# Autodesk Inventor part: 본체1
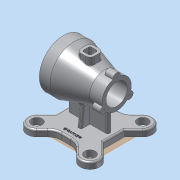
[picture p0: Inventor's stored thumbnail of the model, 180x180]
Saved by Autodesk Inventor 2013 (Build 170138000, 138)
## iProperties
Created: 2018-03
Part Number: 본체1
Material: 알루미늄 6061
Document SubType Name: Modeling
Designer: dgall
Density: 2.71 g/cm^3
Mass: 988.597 g
Surface Area: 870.918 cm^2
Volume: 364.796 cm^3
Author: dgall
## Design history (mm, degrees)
sketch "스케치1"
  geometry: L1 (-50, 0)-(50, 0); L2 (-50, 0)-(-50, 45); L3 (-50, 45)-(-30, 45); L4 (27, 27.5)-(50, 27.5); L5 (50, 27.5)-(50, 0); L6 (-30, 45)-(27, 27.5); 1 further point
  constraints: 12 end point, 3 perpendicular, 1 horizontal, 1 midpoint
  dimensions: "d0" = 90 diameter of L2.end L1; "d2" = 20 distance from line of L3.end L2; "d6" = 55 diameter of L4 L1; "d34" = 77 horizontal distance of L2.end L4.start; "d35" = 100 distance between parallel lines of L5 L2; "d36" = 50 distance from line of L5 point (0, 0)
revolve "회전1" sketch "스케치1" stored, may be unused: angle "d11" = 90 deg
sketch "스케치9"
  geometry: L1 (-50, 0)-(50, 0); L2 (50, 35)-(27, 35); L3 (27, 35)-(27, 26); L4 (27, 26)-(-20, 26); L5 (-20, 26)-(-20, 20); L6 (-20, 20)-(-50, 20); L7 (50, 35)-(50, 0); L8 (-50, 20)-(-50, 0); 1 further point
  constraints: 16 end point, 5 parallel, 2 perpendicular, 1 horizontal, 1 midpoint
  dimensions: "d37" = 100 horizontal distance of L2.start L6.end; "d39" = 70 diameter of L2 L1; "d40" = 23 distance of L2.start L2.end; "d41" = 52 diameter of L4 L1; "d42" = 47 distance between parallel lines of L3 L5; "d43" = 40 diameter of L6 L1; "d44" = 27 distance from line of point (0, 0) L3
revolve "회전3" sketch "스케치9" stored, may be unused: angle "d45" = 90 deg
node "작업 평면2"
sketch "스케치10"
  geometry: L1 (-69.444, 0)-(69.444, 0); L2 (0, 48.611)-(0, -44.444); L3 (-12.5, 12.5)-(12.5, 12.5); L4 (12.5, 12.5)-(12.5, -12.5); L5 (12.5, -12.5)-(-12.5, -12.5); L6 (-12.5, -12.5)-(-12.5, 12.5); 2 further points
  constraints: 12 end point, 2 horizontal, 2 midpoint, 2 parallel, 2 perpendicular, 2 point on line
  dimensions: "d47" = 12.5 distance between parallel lines of L1 L3; "d50" = 12.5 distance between parallel lines of L6 L2; "d51" = 12.5 distance between parallel lines of L4 L2; "d60" = 25 distance between parallel lines of L5 L3
extrude "돌출2" join sketch "스케치10" stored distance "d52" = 10; taper "d53" = 0 deg
sketch "스케치11"
  geometry: L1 (-7.5, 7.5)-(7.5, 7.5); L2 (7.5, 7.5)-(7.5, -7.5); L3 (7.5, -7.5)-(-7.5, -7.5); L4 (-7.5, -7.5)-(-7.5, 7.5); 1 further point
  constraints: 8 end point, 2 parallel, 1 horizontal, 1 perpendicular
  dimensions: "d54" = 7.5 distance from line of L4 point (0, 0); "d55" = 7.5 distance from line of point (0, 0) L2; "d56" = 15 distance between parallel lines of L3 L1; "d57" = 7.5 distance from line of L1 point (0, 0)
extrude "돌출3" cut sketch "스케치11" stored distance "d58" = 10; taper "d59" = 0 deg
fillet "모깎기1" dims "d61" = 8
fillet "모깎기2" dims "d62" = 3
fillet "모깎기3" dims "d63" = 1
node "작업 평면3"
sketch "스케치12"
  geometry: L1 (-45, 45)-(45, 45); L2 (45, 45)-(45, -45); L3 (45, -45)-(-45, -45); L4 (-45, -45)-(-45, 45); L5 (-45, 0)-(45, 0); L6 (60.483, 35.239)-(45, 19.755); L7 (35.239, 60.483)-(19.755, 45); L8 (-65.473, 65.473)-(65.473, -65.473); L9 (62.225, 62.225)-(-62.512, -62.512); L10 (-40.017, 65.473)-(-19.544, 45); L11 (-65.473, 40.017)-(-45, 19.544); L12 (-25.456, 0)-(36.77, 62.225); L13 (-37.056, -62.512)-(-19.544, -45); L14 (0, -25.456)-(62.225, 36.77); L15 (0, 25.456)-(25.456, 0); L16 (45, -19.544)-(65.473, -40.017); L17 (-25.456, 0)-(0, -25.456); L18 (19.544, -45)-(40.017, -65.473); L19 (-62.512, -37.056)-(-33, -7.544); A1 r 70 centre (0, 0) between (60.483, 35.239) and (35.239, 60.483); A2 r 18 centre (-52.745, 52.745) between (-36.227, 59.897) and (-59.897, 36.227); A3 r 18 centre (-49.784, -49.784) between (-62.512, -62.512) and (-37.056, -62.512); A4 r 18 centre (49.497, 49.497) between (60.483, 35.239) and (35.239, 60.483); A5 r 18 centre (52.745, -52.745) between (65.473, -65.473) and (40.017, -65.473); 5 further points
  constraints: 38 end point, 20 point on circle, 18 parallel, 15 point on line, 6 midpoint, 5 centre point, 3 perpendicular, 1 coincident, 1 horizontal, 1 tangent
  dimensions: "d65" = 45 distance from line of L4 point (0, 0); "d67" = 45 distance from line of point (0, 0) L1; "d69" = 90 distance between parallel lines of L3 L1; "d70" = 90 distance between parallel lines of L2 L4; "d71" = 140 diameter of A1; "d74" = 36 diameter of A3; "d77" = 36 diameter of A4; "d78" = 36 diameter of A5; "d83" = 45 deg angle of L5 L8; "d86" = 36 diameter of A2; "d87" = 45 deg angle of L5 L9; "d90" = 18 distance between parallel lines of L13 L9
extrude "돌출4" join sketch "스케치12" distance "d92" = 12; taper "d93" = 0 deg
sketch "스케치13"
  geometry: L1 (36.77, 62.225)-(-12.728, 12.728) reference; L2 (-12.728, 12.728)-(-45, 45) reference; L3 (-45, 45)-(-19.544, 45) reference; L4 (-45, 19.544)-(-45, -32.432) reference; L5 (-19.544, 45)-(19.544, 45); 1 further point
  constraints: 2 end point, 1 perpendicular, 1 point on line
extrude "돌출5" join sketch "스케치13" distance "d94" = 12; taper "d95" = 0 deg
sketch "스케치14"
  geometry: L1 (-32.432, -45)-(19.544, -45) reference; L2 (-65.473, 40.017)-(-45, 19.544) reference; L3 (-45, 19.544)-(-45, -32.432) reference; L4 (-37.056, -62.512)-(-19.544, -45); L5 (-62.512, -37.056)-(-45, -19.544); A1 r 18 centre (-49.784, -49.784) between (-45, -32.432) and (-32.432, -45) reference; 1 further point
  constraints: 4 end point, 2 point on circle, 2 point on line, 1 parallel, 1 perpendicular
  dimensions: "d96" = 18 distance from line of L4 point (0, 0); "d97" = 18 distance from line of point (0, 0) L5
extrude "돌출6" join sketch "스케치14" distance "d98" = 12; taper "d99" = 0 deg
fillet "모깎기4" dims "d100" = 25
sketch "스케치18"
  geometry: L1 (-45, 19.544)-(-45, -19.544) reference; L2 (0, 0)-(-37, 0); L3 (0, 0)-(37, 0); L4 (-37.056, -4)-(36.944, -4); L5 (-37.056, 4)-(36.944, 4); L6 (-37.056, 4)-(-37.056, -4); L7 (36.944, 4)-(36.944, -4)
  constraints: 12 end point, 2 equal length, 2 perpendicular
  dimensions: "d111" = 4 distance between parallel lines of L5 L2; "d112" = 4 distance between parallel lines of L2 L4; "d115" = 74 distance between parallel lines of L6 L7
extrude "돌출7" join sketch "스케치18" stored distance "d116" = 12; taper "d117" = 0 deg
sketch "스케치20"
  geometry: L1 (-24, -109.58)-(-24, -45); L2 (-24, -109.58)-(-18, -41); L3 (-19.544, -70)-(-37.056, -70) reference; 1 further point
  constraints: 4 end point, 2 point on line, 1 vertical
  dimensions: "d118" = 24 distance from line of point (0, 0) L1; "d119" = 95 deg angle of L3 L2
feature "리브1" sketch "스케치20" dims "d120" = 1, "d121" = 8, "d122" = 0, "d123" = 0, "d124" = 1, "d125" = 1
sketch "스케치21"
  geometry: L1 (24, -38)-(24, -138.301); L2 (24, -138.301)-(14, -24); L3 (19.544, -70)-(36.77, -70) reference; 1 further point
  constraints: 4 end point, 2 point on line, 1 vertical
  dimensions: "d126" = 24 distance from line of point (0, 0) L1; "d127" = 95 deg angle of L3 L2
feature "리브2" sketch "스케치21" dims "d128" = 1, "d129" = 8, "d130" = 0, "d131" = 0, "d132" = 1, "d133" = 1
fillet "모깎기5" dims "d134" = 3
fillet "모깎기6" dims "d135" = 3
node "작업 평면4"
sketch "스케치24" dims "d139" = 55
  geometry: L1 (-32.921, 0)-(28.532, 0); C1 r 7 at (-27.5, 0); C2 r 7 at (13.75, -23.816); C3 r 7 at (13.75, 23.816); 2 further points
  constraints: 3 centre point, 2 end point, 2 point on line, 1 coincident, 1 horizontal, 1 horizontal alignment, 9 other
  dimensions: "d141" = 14 diameter of C1; "d144" = 360 deg dimension on point (0, 0) C1.centre (derived)
extrude "돌출8" join sketch "스케치24" distance "d146" = 15; taper "d147" = 0 deg
sketch "스케치25"
  geometry: C1 r 2 at (-27.5, 0); C2 r 2 at (13.75, 23.816); C3 r 2 at (13.75, -23.816); A1 r 7 centre (-27.5, 0) between (-26.609, 6.943) and (-26.609, -6.943) reference; A2 r 7 centre (13.75, -23.816) between (7.292, -26.516) and (19.317, -19.573) reference; A3 r 7 centre (13.75, 23.816) between (19.317, 19.573) and (7.292, 26.516) reference
  constraints: 3 centre point, 3 coincident
  dimensions: "d148" = 4 diameter of C1; "d150" = 4 diameter of C3; "d151" = 4 diameter of C2
hole "구멍1" sketch "스케치25" at (-27.5, 0), (13.75, -23.816), (13.75, 23.816) diameter "d152" = 2.459; stored, may be unused: countersink angle "d156" = 90 deg, drill point angle "d158" = 118 deg; dims "d153" = 9, "d154" = 4, "d155" = 2, "d157" = 11
sketch "스케치26"
  geometry: L1 (40, 0)-(-40, 0); C1 r 35 at (0, 0) reference; C2 r 45 at (0, 0) reference; C3 r 2 at (40, 0); C4 r 2 at (20, 34.641); C5 r 2 at (-20, 34.641); C6 r 2 at (-40, 0); C7 r 2 at (-20, -34.641); C8 r 2 at (20, -34.641); A1 r 40 centre (0, 0) between (40, 0) and (-40, 0)
  constraints: 7 centre point, 3 point on circle, 2 end point, 1 coincident, 13 other
  dimensions: "d159" = 80 diameter of A1; "d161" = 4 diameter of C3; "d164" = 360 deg dimension on C1.centre C3.centre (derived)
hole "구멍2" sketch "스케치26" at (40, 0), (20, -34.641), (-20, -34.641), (-40, 0), (-20, 34.641), (20, 34.641) diameter "d166" = 2.459; stored, may be unused: countersink angle "d170" = 90 deg, drill point angle "d172" = 118 deg; dims "d167" = 9, "d168" = 4, "d169" = 2, "d171" = 11
sketch "스케치27"
  geometry: C1 r 10 at (-52.745, 52.745); C2 r 10 at (49.497, 49.497); C3 r 10 at (52.745, -52.745); C4 r 10 at (-49.784, -49.784); A1 r 18 centre (52.745, -52.745) between (40.017, -65.473) and (65.473, -40.017) reference; A2 r 18 centre (49.497, 49.497) between (62.225, 36.77) and (36.77, 62.225) reference; A3 r 18 centre (-52.745, 52.745) between (-40.017, 65.473) and (-65.473, 40.017) reference; A4 r 18 centre (-49.784, -49.784) between (-62.512, -37.056) and (-37.056, -62.512) reference; 1 further point
  constraints: 4 centre point, 4 coincident
  dimensions: "d173" = 20 diameter of C1; "d175" = 20 diameter of C2; "d176" = 20 diameter of C4; "d177" = 20 diameter of C3
extrude "돌출9" cut sketch "스케치27" stored distance "d178" = 15; taper "d179" = 0 deg
fillet "모깎기7" dims "d180" = 3
sketch "스케치28"
  geometry: L1 (-14.152, -32.598)-(14.152, -32.598); L2 (14.152, -32.598)-(14.152, -37.402); L3 (14.152, -37.402)-(-14.152, -37.402); L4 (-14.152, -37.402)-(-14.152, -32.598); L5 (-14.152, -35)-(14.152, -35); L6 (0, -32.598)-(0, -37.402); L7 (45, -19.544)-(45, 19.544) reference; 1 further point
  constraints: 4 end point, 4 midpoint, 2 other
  dimensions: "d181" = 35 distance from line of L5 point (0, 0); "d182" = 45 distance between parallel lines of L7 L6
extrude "돌출10" join sketch "스케치28" distance "d183" = 0.5; taper "d184" = 0 deg
node "솔리드1"
other parameters: "d46" = 45, "d64" = -82, "d84" = 18, "d85" = 18, "d88" = 18, "d89" = 18, "d138" = -15
